(* Logix 5000 project; controller Optix_CM_rev0 vendor 1 type 14 code 217 rev 38.11; software revision 38.00 *)

TASK MainTask (continuous, watchdog 500 ms) : MainProgram

MODULES
   Local : vendor 1 type 14 code 217 (5069 0, rev 38.11)
      Dyn_0001 : vendor 1 type 109 code 72 (Ethernet 192.168.1.3, rev 4.11, StandardDataDriven RPI 80 ms)
END_MODULES

PROGRAM MainProgram   (* main routine MainRoutine *)

ROUTINE MainRoutine   (* ladder *)
END_ROUTINE
END_PROGRAM
